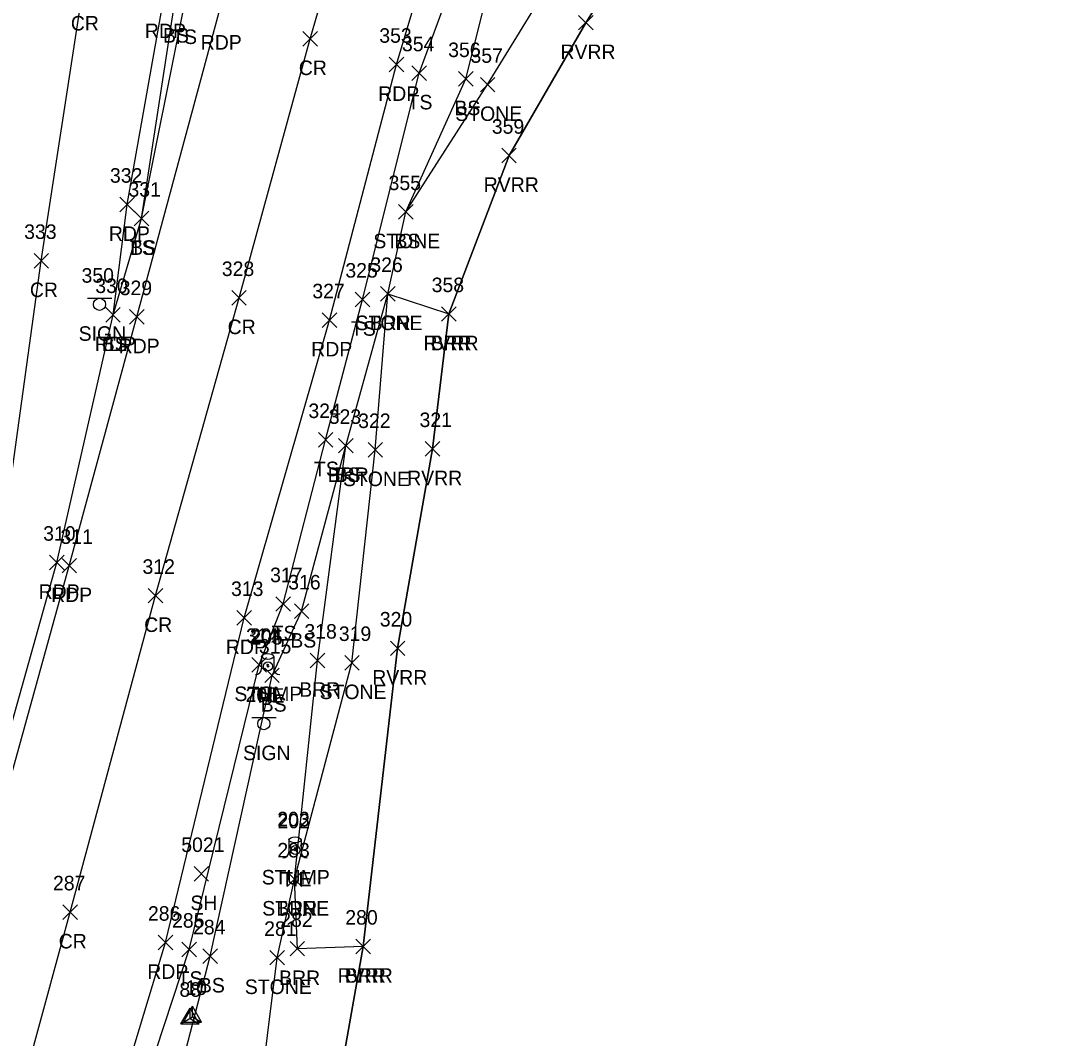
# Model space of a CAD drawing. Extents: x 1482574 to 1485769, y 580696 to 595649.
# Drawn here: x 1483632.5 to 1483775.9, y 584131.3 to 584271.3 of the extents above; entities that cross this region are included whole.
import ezdxf

# ---------------------------------------------------------------- set-up
doc = ezdxf.new("R2010")
doc.units = 0
for name, color, linetype in [('C_A', 7, 'Continuous'), ('C_I', 7, 'Continuous'), ('CBP', 7, 'Continuous'), ('CPSM', 7, 'Continuous'), ('L_A', 7, 'Continuous'), ('L_I', 7, 'Continuous'), ('L_TIC', 7, 'Continuous'), ('LABL', 7, 'Continuous'), ('LASF', 7, 'Continuous'), ('LAWE', 7, 'Continuous'), ('LELB', 7, 'Continuous'), ('LSOGP', 7, 'Continuous'), ('LTS', 7, 'Continuous'), ('P_A', 7, 'Continuous'), ('P_I', 7, 'Continuous'), ('P_TIC', 7, 'Continuous'), ('PET', 7, 'Continuous'), ('PRC', 7, 'Continuous'), ('S_A', 7, 'Continuous'), ('S_I', 7, 'Continuous'), ('SSGN', 7, 'Continuous')]:
    doc.layers.add(name, color=color, linetype=linetype)

msp = doc.modelspace()

# ---------------------------------------------------------------- linework, layer by layer
at = {"layer": 'CBP'}
for centre, radius in [((1483666.56, 584182.5), 0.625), ((1483666.56, 584182.5), 0.0833), ((1483670.3, 584157.22), 0.625), ((1483670.3, 584157.22), 0.0833)]:
    msp.add_circle(centre, radius, dxfattribs=at)
at = {"layer": 'CPSM'}
for p, q in [((1483654.57, 584133.3), (1483655.82, 584135.47)), ((1483654.91, 584133.56), (1483656.16, 584135.72)), ((1483657.07, 584133.3), (1483655.82, 584135.47)), ((1483655.82, 584134.03), (1483655.82, 584135.47)), ((1483657.41, 584133.56), (1483656.16, 584135.72)), ((1483656.16, 584134.28), (1483656.16, 584135.72)), ((1483654.57, 584133.3), (1483655.82, 584134.03)), ((1483654.91, 584133.56), (1483656.16, 584134.28)), ((1483655.82, 584134.03), (1483655.82, 584134.03)), ((1483655.82, 584134.03), (1483657.07, 584133.3)), ((1483656.16, 584134.28), (1483656.16, 584134.28)), ((1483656.16, 584134.28), (1483657.41, 584133.56)), ((1483654.57, 584133.3), (1483657.07, 584133.3)), ((1483654.91, 584133.56), (1483657.41, 584133.56))]:
    msp.add_line(p, q, dxfattribs=at)
at = {"layer": 'L_TIC'}
for points in [[(1483709.3, 584270.09), (1483711.3, 584272.09)], [(1483711.3, 584270.09), (1483709.3, 584272.09)], [(1483686.36, 584263.16), (1483688.36, 584265.16)], [(1483688.36, 584263.16), (1483686.36, 584265.16)], [(1483692.77, 584262.36), (1483694.77, 584264.36)], [(1483694.77, 584262.36), (1483692.77, 584264.36)], [(1483695.78, 584261.57), (1483697.78, 584263.57)], [(1483697.78, 584261.57), (1483695.78, 584263.57)], [(1483698.73, 584251.81), (1483700.73, 584253.81)], [(1483700.73, 584251.81), (1483698.73, 584253.81)], [(1483684.51, 584244.05), (1483686.51, 584246.05)], [(1483686.51, 584244.05), (1483684.51, 584246.05)], [(1483684.51, 584244.05), (1483686.51, 584246.05)], [(1483686.51, 584244.05), (1483684.51, 584246.05)], [(1483648.14, 584243.14), (1483650.14, 584245.14)], [(1483650.14, 584243.14), (1483648.14, 584245.14)], [(1483648.14, 584243.14), (1483650.14, 584245.14)], [(1483650.14, 584243.14), (1483648.14, 584245.14)], [(1483682.05, 584232.78), (1483684.05, 584234.78)], [(1483684.05, 584232.78), (1483682.05, 584234.78)], [(1483682.05, 584232.78), (1483684.05, 584234.78)], [(1483684.05, 584232.78), (1483682.05, 584234.78)], [(1483678.56, 584232.01), (1483680.56, 584234.01)], [(1483680.56, 584232.01), (1483678.56, 584234.01)], [(1483644.22, 584229.89), (1483646.22, 584231.89)], [(1483646.22, 584229.89), (1483644.22, 584231.89)], [(1483690.45, 584230.01), (1483692.45, 584232.01)], [(1483692.45, 584230.01), (1483690.45, 584232.01)], [(1483690.45, 584230.01), (1483692.45, 584232.01)], [(1483692.45, 584230.01), (1483690.45, 584232.01)], [(1483673.48, 584212.68), (1483675.48, 584214.68)], [(1483675.48, 584212.68), (1483673.48, 584214.68)], [(1483676.27, 584211.88), (1483678.27, 584213.88)], [(1483678.27, 584211.88), (1483676.27, 584213.88)], [(1483676.27, 584211.88), (1483678.27, 584213.88)], [(1483678.27, 584211.88), (1483676.27, 584213.88)], [(1483680.32, 584211.31), (1483682.32, 584213.31)], [(1483682.32, 584211.31), (1483680.32, 584213.31)], [(1483688.2, 584211.44), (1483690.2, 584213.44)], [(1483690.2, 584211.44), (1483688.2, 584213.44)], [(1483667.64, 584190.09), (1483669.64, 584192.09)], [(1483669.64, 584190.09), (1483667.64, 584192.09)], [(1483670.18, 584189.09), (1483672.18, 584191.09)], [(1483672.18, 584189.09), (1483670.18, 584191.09)], [(1483683.39, 584183.99), (1483685.39, 584185.99)], [(1483685.39, 584183.99), (1483683.39, 584185.99)], [(1483672.36, 584182.32), (1483674.36, 584184.32)], [(1483674.36, 584182.32), (1483672.36, 584184.32)], [(1483677.11, 584182), (1483679.11, 584184)], [(1483679.11, 584182), (1483677.11, 584184)], [(1483664.33, 584181.72), (1483666.33, 584183.72)], [(1483666.33, 584181.72), (1483664.33, 584183.72)], [(1483666.1, 584180.27), (1483668.1, 584182.27)], [(1483668.1, 584180.27), (1483666.1, 584182.27)], [(1483656.38, 584152.96), (1483658.38, 584154.96)], [(1483658.38, 584152.96), (1483656.38, 584154.96)], [(1483669.21, 584152.21), (1483671.21, 584154.21)], [(1483671.21, 584152.21), (1483669.21, 584154.21)], [(1483669.21, 584152.21), (1483671.21, 584154.21)], [(1483671.21, 584152.21), (1483669.21, 584154.21)], [(1483654.7, 584142.54), (1483656.7, 584144.54)], [(1483656.7, 584142.54), (1483654.7, 584144.54)], [(1483669.59, 584142.65), (1483671.59, 584144.65)], [(1483671.59, 584142.65), (1483669.59, 584144.65)], [(1483678.64, 584142.96), (1483680.64, 584144.96)], [(1483680.64, 584142.96), (1483678.64, 584144.96)], [(1483678.64, 584142.96), (1483680.64, 584144.96)], [(1483680.64, 584142.96), (1483678.64, 584144.96)], [(1483657.6, 584141.62), (1483659.6, 584143.62)], [(1483659.6, 584141.62), (1483657.6, 584143.62)], [(1483666.82, 584141.41), (1483668.82, 584143.41)], [(1483668.82, 584141.41), (1483666.82, 584143.41)]]:
    msp.add_lwpolyline(points, dxfattribs=at)
at = {"layer": 'LABL'}
msp.add_lwpolyline([(1483679.64, 584143.96), (1483670.59, 584143.65), (1483670.21, 584153.21), (1483673.36, 584183.32), (1483677.27, 584212.88), (1483683.05, 584233.78), (1483691.45, 584231.01)], dxfattribs=at)
at = {"layer": 'LASF'}
msp.add_lwpolyline([(1483671.48, 584047.54), (1483666.41, 584073.49), (1483662.71, 584087.1), (1483662.98, 584100.25), (1483663.82, 584110.32), (1483667.82, 584142.41), (1483670.21, 584153.21), (1483678.11, 584183), (1483681.32, 584212.31), (1483683.05, 584233.78), (1483685.51, 584245.05), (1483696.78, 584262.57), (1483705.7, 584277.17), (1483710.79, 584290.29), (1483715.48, 584313.49), (1483717.15, 584337.83), (1483717.97, 584359.1), (1483719.66, 584377.86), (1483716.84, 584387.63), (1483711.61, 584397.92), (1483702.45, 584409.36), (1483691.17, 584424.34), (1483688.63, 584428.24), (1483691.21, 584429.95)], dxfattribs=at)
at = {"layer": 'LAWE'}
msp.add_lwpolyline([(1483682.09, 584047.37), (1483679.01, 584062.67), (1483675.83, 584076.1), (1483673.01, 584093.17), (1483673.93, 584111.51), (1483679.64, 584143.96), (1483684.39, 584184.99), (1483689.2, 584212.44), (1483691.45, 584231.01), (1483699.73, 584252.81), (1483710.3, 584271.09), (1483715.87, 584279.92), (1483724.32, 584288.73), (1483732.24, 584294.29), (1483734.05, 584295.82), (1483747.44, 584305.84), (1483760.72, 584319.04), (1483775.88, 584327.57)], dxfattribs=at)
at = {"layer": 'LELB'}
for points in [[(1483645.22, 584230.89), (1483649.14, 584244.14), (1483653.65, 584273.35), (1483658.76, 584297.64), (1483667.17, 584336.68), (1483673.13, 584380.76), (1483673.02, 584387.76), (1483681.21, 584387.96), (1483680.49, 584397.19), (1483684.25, 584413.71)], [(1483649.14, 584244.14), (1483654.95, 584273.16), (1483661.52, 584296.92), (1483669.21, 584336.55), (1483678.21, 584375.46), (1483679.04, 584384.52), (1483684.8, 584386.22)], [(1483609.7, 583968.11), (1483614.54, 583983.93), (1483615.47, 583999.91), (1483618.2, 584010.03), (1483620.48, 584023), (1483628.04, 584045.27), (1483636.71, 584078.69), (1483645.46, 584112.42), (1483655.7, 584143.54), (1483665.33, 584182.72), (1483668.64, 584191.09), (1483674.48, 584213.68), (1483679.56, 584233.01), (1483687.36, 584264.16), (1483694.8, 584284.35), (1483705.09, 584327.19), (1483710.94, 584361.26), (1483712.22, 584376.12), (1483713.45, 584382.29)], [(1483685.51, 584245.05), (1483693.77, 584263.36), (1483698.59, 584282.49), (1483708.81, 584322.83), (1483713.69, 584344.63)], [(1483618.2, 584010.03), (1483623.29, 584011.26), (1483626.83, 584023.46), (1483628.7, 584035.25), (1483633.76, 584044.44), (1483640.78, 584078.11), (1483649.78, 584108.58), (1483658.6, 584142.62), (1483667.1, 584181.27), (1483671.18, 584190.09), (1483677.27, 584212.88)]]:
    msp.add_lwpolyline(points, dxfattribs=at)
at = {"layer": 'LSOGP'}
msp.add_lwpolyline([(1483715.87, 584279.92), (1483710.3, 584271.09), (1483699.73, 584252.81), (1483691.45, 584231.01), (1483689.2, 584212.44), (1483684.39, 584184.99), (1483679.64, 584143.96), (1483673.93, 584111.51), (1483673.01, 584093.17), (1483675.83, 584076.1), (1483679.01, 584062.67), (1483682.09, 584047.37), (1483681.18, 584015.9)], dxfattribs=at)
at = {"layer": 'LTS'}
for p, q in [((1483665.66, 584183.87), (1483665.66, 584182.2)), ((1483666.5, 584182.72), (1483666.5, 584182.72)), ((1483666.5, 584182.72), (1483666.5, 584182.72)), ((1483666.5, 584182.7), (1483666.5, 584182.7)), ((1483667.33, 584183.7), (1483667.33, 584183.87)), ((1483667.33, 584183.87), (1483667.33, 584182.2)), ((1483669.43, 584158.63), (1483669.43, 584156.97)), ((1483671.1, 584158.47), (1483671.1, 584158.63)), ((1483671.1, 584158.63), (1483671.1, 584156.97)), ((1483670.27, 584157.49), (1483670.27, 584157.49)), ((1483670.27, 584157.49), (1483670.27, 584157.49)), ((1483670.27, 584157.47), (1483670.27, 584157.47))]:
    msp.add_line(p, q, dxfattribs=at)
for centre in [(1483666.5, 584182.72), (1483670.27, 584157.49)]:
    msp.add_circle(centre, 0.0833, dxfattribs=at)
for centre, start, end in [((1483664.83, 584182.2), 270, 360), ((1483668.16, 584182.2), 180, 270), ((1483668.6, 584156.97), 270, 360), ((1483671.93, 584156.97), 180, 270)]:
    msp.add_arc(centre, 0.833, start, end, dxfattribs=at)
for centre in [(1483666.5, 584183.87), (1483670.27, 584158.63)]:
    msp.add_ellipse(centre, major_axis=(-0.833, 0), ratio=0.5, dxfattribs=at)
at = {"layer": 'P_TIC'}
for points in [[(1483671.36, 584267.88), (1483673.36, 584269.88)], [(1483673.36, 584267.88), (1483671.36, 584269.88)], [(1483683.23, 584264.33), (1483685.23, 584266.33)], [(1483685.23, 584264.33), (1483683.23, 584266.33)], [(1483646.15, 584245.07), (1483648.15, 584247.07)], [(1483648.15, 584245.07), (1483646.15, 584247.07)], [(1483634.34, 584237.33), (1483636.34, 584239.33)], [(1483636.34, 584237.33), (1483634.34, 584239.33)], [(1483661.56, 584232.23), (1483663.56, 584234.23)], [(1483663.56, 584232.23), (1483661.56, 584234.23)], [(1483644.22, 584229.89), (1483646.22, 584231.89)], [(1483646.22, 584229.89), (1483644.22, 584231.89)], [(1483647.5, 584229.6), (1483649.5, 584231.6)], [(1483649.5, 584229.6), (1483647.5, 584231.6)], [(1483674.01, 584229.16), (1483676.01, 584231.16)], [(1483676.01, 584229.16), (1483674.01, 584231.16)], [(1483636.48, 584195.8), (1483638.48, 584197.8)], [(1483638.48, 584195.8), (1483636.48, 584197.8)], [(1483638.2, 584195.36), (1483640.2, 584197.36)], [(1483640.2, 584195.36), (1483638.2, 584197.36)], [(1483650.07, 584191.24), (1483652.07, 584193.24)], [(1483652.07, 584191.24), (1483650.07, 584193.24)], [(1483662.26, 584188.19), (1483664.26, 584190.19)], [(1483664.26, 584188.19), (1483662.26, 584190.19)], [(1483638.31, 584147.68), (1483640.31, 584149.68)], [(1483640.31, 584147.68), (1483638.31, 584149.68)], [(1483651.44, 584143.5), (1483653.44, 584145.5)], [(1483653.44, 584143.5), (1483651.44, 584145.5)]]:
    msp.add_lwpolyline(points, dxfattribs=at)
at = {"layer": 'PET'}
for points in [[(1483581.83, 583972.99), (1483588.38, 584007.28), (1483591.08, 584021.15), (1483598.25, 584047.59), (1483606.6, 584077.17), (1483615.66, 584112.76), (1483626.75, 584151.48), (1483639.2, 584196.36), (1483648.5, 584230.6), (1483659.8, 584272.39), (1483666.33, 584295.08), (1483675.64, 584335.04), (1483684.8, 584386.22), (1483696.48, 584384.63), (1483708.99, 584382.82)], [(1483606.55, 583968.55), (1483613.49, 584003.98), (1483618.43, 584023.3), (1483624.77, 584045.54), (1483634.53, 584079.05), (1483643.94, 584116.41), (1483652.44, 584144.5), (1483663.26, 584189.19), (1483675.01, 584230.16), (1483684.23, 584265.33), (1483690.21, 584285.32), (1483701.13, 584329.73), (1483708.99, 584382.82)], [(1483594.54, 584046.02), (1483604.39, 584076.98), (1483614.34, 584113.18), (1483620.6, 584139.06), (1483624.66, 584151.24), (1483637.48, 584196.8), (1483645.22, 584230.89), (1483647.15, 584246.07), (1483652.12, 584273.97)]]:
    msp.add_lwpolyline(points, dxfattribs=at)
at = {"layer": 'PRC'}
for points in [[(1483620.6, 584139.06), (1483622.76, 584151.25), (1483629.8, 584198.38), (1483635.34, 584238.33), (1483640.98, 584275.02), (1483645.1, 584300.76), (1483651.33, 584343.69), (1483657.04, 584382.59), (1483662.41, 584419.09), (1483666.56, 584457.85), (1483673.34, 584508.06), (1483676.92, 584541.04), (1483679.4, 584571.58), (1483681.28, 584596.25), (1483683.38, 584631.91)], [(1483594.14, 583970.96), (1483600.75, 584006.37), (1483610.42, 584043.26), (1483619.21, 584075.32), (1483628.72, 584109.95), (1483639.31, 584148.68), (1483651.07, 584192.24), (1483662.56, 584233.23), (1483672.36, 584268.88), (1483678.88, 584291.31), (1483688.34, 584333), (1483696.48, 584384.63)]]:
    msp.add_lwpolyline(points, dxfattribs=at)
at = {"layer": 'SSGN'}
for p, q in [((1483641.7, 584233.17), (1483645.03, 584233.17)), ((1483643.35, 584232.33), (1483643.35, 584232.33)), ((1483664.33, 584175.45), (1483667.66, 584175.45)), ((1483665.97, 584174.62), (1483665.97, 584174.62))]:
    msp.add_line(p, q, dxfattribs=at)
for centre in [(1483643.35, 584232.33), (1483665.97, 584174.62)]:
    msp.add_circle(centre, 0.833, dxfattribs=at)

# ---------------------------------------------------------------- texts
at = {"layer": 'C_A'}
for p in [(1483664.64, 584177.5), (1483668.38, 584152.22)]:
    msp.add_text('TIE', height=2, dxfattribs=at).set_placement(p)
at = {"layer": 'C_I'}
for s, p in [('205', (1483664.12, 584185.5)), ('202', (1483667.86, 584160.22)), ('88', (1483654.36, 584137.03)), ('10', (1483655.17, 584137.28))]:
    msp.add_text(s, height=2, dxfattribs=at).set_placement(p)
at = {"layer": 'L_A'}
for s, p in [('BS', (1483652.09, 584268.35)), ('TS', (1483653.36, 584268.16)), ('RVRR', (1483706.81, 584266.09)), ('TS', (1483685.77, 584259.16)), ('BS', (1483692.21, 584258.36)), ('STONE', (1483692.33, 584257.57)), ('RVRR', (1483696.25, 584247.81)), ('STONE', (1483681.05, 584240.05)), ('BS', (1483683.95, 584240.05)), ('TS', (1483647.55, 584239.14)), ('BS', (1483647.58, 584239.14)), ('TS', (1483677.97, 584228.01)), ('STONE', (1483678.6, 584228.78)), ('BRR', (1483680.54, 584228.78)), ('BS', (1483643.66, 584225.89)), ('RVRR', (1483687.96, 584226.01)), ('BRR', (1483688.93, 584226.01)), ('TS', (1483672.88, 584208.68)), ('BRR', (1483674.76, 584207.88)), ('BS', (1483675.71, 584207.88)), ('STONE', (1483676.87, 584207.31)), ('RVRR', (1483685.71, 584207.44)), ('TS', (1483667.05, 584186.09)), ('BS', (1483669.62, 584185.09)), ('RVRR', (1483680.9, 584179.99)), ('STUMP', (1483661.92, 584177.73)), ('TS', (1483663.74, 584177.72)), ('BRR', (1483670.85, 584178.32)), ('STONE', (1483673.65, 584178)), ('BS', (1483665.54, 584176.27)), ('STUMP', (1483665.69, 584152.49)), ('SH', (1483655.87, 584148.96)), ('STONE', (1483665.75, 584148.21)), ('BRR', (1483667.69, 584148.21)), ('RVRR', (1483676.15, 584138.96)), ('BRR', (1483677.13, 584138.96)), ('TS', (1483654.11, 584138.54)), ('BS', (1483657.04, 584137.62)), ('BRR', (1483668.08, 584138.65)), ('STONE', (1483663.36, 584137.41))]:
    msp.add_text(s, height=2, dxfattribs=at).set_placement(p)
at = {"layer": 'L_I'}
for s, p in [('354', (1483684.99, 584267.16)), ('356', (1483691.35, 584266.36)), ('357', (1483694.42, 584265.57)), ('359', (1483697.36, 584255.81)), ('355', (1483683.15, 584248.05)), ('355', (1483683.15, 584248.05)), ('331', (1483647.34, 584247.14)), ('331', (1483647.34, 584247.14)), ('326', (1483680.64, 584236.78)), ('326', (1483680.64, 584236.78)), ('325', (1483677.2, 584236.01)), ('330', (1483642.77, 584233.89)), ('358', (1483689.08, 584234.01)), ('358', (1483689.08, 584234.01)), ('324', (1483672.11, 584216.68)), ('323', (1483674.91, 584215.88)), ('323', (1483674.91, 584215.88)), ('322', (1483678.96, 584215.31)), ('321', (1483687.41, 584215.44)), ('317', (1483666.84, 584194.09)), ('316', (1483669.33, 584193.09)), ('320', (1483681.94, 584187.99)), ('318', (1483671.56, 584186.32)), ('314', (1483663.53, 584185.72)), ('204', (1483664.05, 584185.73)), ('319', (1483676.3, 584186)), ('315', (1483665.3, 584184.27)), ('203', (1483667.82, 584160.49)), ('5021', (1483654.61, 584156.96)), ('283', (1483667.84, 584156.21)), ('283', (1483667.84, 584156.21)), ('285', (1483653.34, 584146.54)), ('282', (1483668.23, 584146.65)), ('280', (1483677.19, 584146.96)), ('280', (1483677.19, 584146.96)), ('284', (1483656.23, 584145.62)), ('281', (1483666.02, 584145.41))]:
    msp.add_text(s, height=2, dxfattribs=at).set_placement(p)
at = {"layer": 'P_A'}
for s, p in [('CR', (1483639.41, 584270.02)), ('RDP', (1483649.6, 584268.97)), ('RDP', (1483657.29, 584267.39)), ('CR', (1483670.79, 584263.88)), ('RDP', (1483681.72, 584260.33)), ('RDP', (1483644.64, 584241.07)), ('CR', (1483633.77, 584233.33)), ('CR', (1483660.99, 584228.23)), ('RDP', (1483642.71, 584225.89)), ('RDP', (1483645.99, 584225.6)), ('RDP', (1483672.5, 584225.16)), ('RDP', (1483634.97, 584191.8)), ('RDP', (1483636.69, 584191.36)), ('CR', (1483649.5, 584187.24)), ('RDP', (1483660.75, 584184.19)), ('CR', (1483637.74, 584143.68)), ('RDP', (1483649.93, 584139.5))]:
    msp.add_text(s, height=2, dxfattribs=at).set_placement(p)
at = {"layer": 'P_I'}
for s, p in [('353', (1483681.87, 584268.33)), ('332', (1483644.79, 584249.07)), ('333', (1483632.98, 584241.33)), ('328', (1483660.19, 584236.23)), ('330', (1483642.77, 584233.89)), ('329', (1483646.13, 584233.6)), ('327', (1483672.65, 584233.16)), ('310', (1483635.6, 584199.8)), ('311', (1483637.98, 584199.36)), ('312', (1483649.27, 584195.24)), ('313', (1483661.46, 584192.19)), ('287', (1483636.95, 584151.68)), ('286', (1483650.02, 584147.5))]:
    msp.add_text(s, height=2, dxfattribs=at).set_placement(p)
at = {"layer": 'S_A'}
for p in [(1483640.48, 584227.31), (1483663.11, 584169.6)]:
    msp.add_text('SIGN', height=2, dxfattribs=at).set_placement(p)
at = {"layer": 'S_I'}
for s, p in [('350', (1483640.88, 584235.31)), ('206', (1483663.46, 584177.6))]:
    msp.add_text(s, height=2, dxfattribs=at).set_placement(p)

doc.saveas('drawing.dxf')
